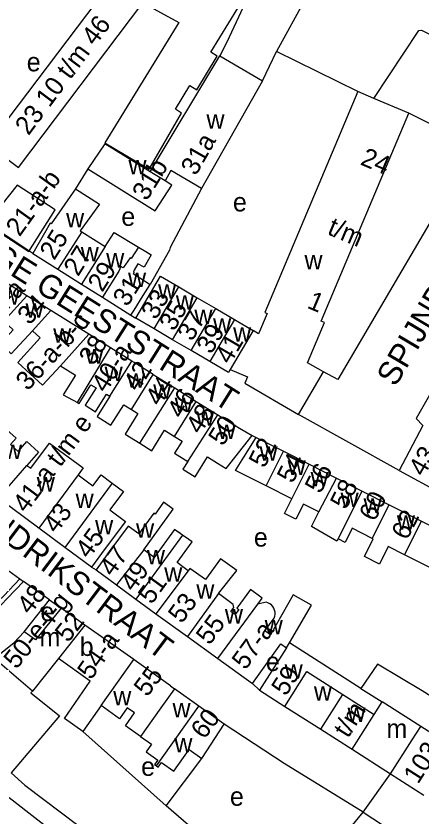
# Model space of a CAD drawing. Extents: x 160673 to 161924, y 382258 to 384145.
# Drawn here: x 160974.8 to 161061.5, y 383019.8 to 383190.7 of the extents above; entities that cross this region are included whole.
import ezdxf

# ---------------------------------------------------------------- set-up
doc = ezdxf.new("R2010")
doc.units = 0
for name, color, linetype in [('BLT_Basislijn', 7, 'Continuous'), ('BLT_Bebouwing', 7, 'Continuous'), ('BLT_Centroide', 7, 'Continuous'), ('BLT_Huisnummer', 7, 'Continuous'), ('BLT_Huisnummer_ tussenligend', 7, 'Continuous'), ('BLT_Huisnummer_reeks', 7, 'Continuous'), ('BLT_Huisnummer_zonder_bebouwing', 7, 'Continuous'), ('BLT_Onderverdeling_panden', 7, 'Continuous'), ('BLT_Plantopo', 7, 'Continuous'), ('BLT_Straatnaam', 7, 'Continuous'), ('BLT_Vlakafsluiter', 7, 'Continuous')]:
    doc.layers.add(name, color=color, linetype=linetype)

msp = doc.modelspace()

# ---------------------------------------------------------------- linework, layer by layer
at = {"layer": 'BLT_Basislijn'}
for p, q in [((161036.77, 383194.74), (161030.43, 383183.09)), ((161027.44, 383176.86), (161030.43, 383183.09)), ((161047.75, 383174.53), (161030.43, 383183.09)), ((161072.75, 383162.91), (161058.69, 383169.92)), ((160990.08, 383158.05), (160987.44, 383153.76)), ((160999.32, 383126.81), (161000.35, 383126.21)), ((161025.23, 383101.17), (161026.06, 383100.78)), ((160990.9, 383073.09), (160991.86, 383072.52)), ((160975.61, 383070.61), (160976.35, 383070.05)), ((160981.93, 383066.1), (160984.38, 383064.36)), ((161026.77, 383046.81), (161025.24, 383048.28)), ((161006.81, 383022.18), (161014.46, 383032.26)), ((161032.47, 383000.08), (161006.81, 383022.18))]:
    msp.add_line(p, q, dxfattribs=at)
for points in [[(161031.09, 383209.4), (161019.81, 383185.12), (161018.27, 383182.14)], [(161051.19, 383173.08), (161060.81, 383187.57), (161061.4, 383187.65), (161069.83, 383183.47), (161071.59, 383182.56)], [(161072.75, 383162.91), (161043.52, 383113.14), (161040.44, 383114.74)], [(161014.37, 383153.9), (161007.71, 383141.3), (161007.56, 383140.71), (161003.41, 383133.39)], [(161088.85, 383154.88), (161060.21, 383104.82), (161061.64, 383103.3)], [(160978.35, 383140.02), (160971.24, 383144.7), (160965.71, 383148.08)], [(161056.57, 383093.7), (161035.09, 383105.63)], [(161048.92, 383020.84), (161032.03, 383031.2), (161019.19, 383039.6)], [(161006.81, 383022.18), (160989.02, 383038.01)], [(160973.74, 383029.17), (160976.69, 383026.54), (161003.35, 383006.47), (160993.29, 382992.74)], [(160963.06, 383015.22), (160978.82, 382996.13), (160992.96, 383008.58), (160973.33, 383023.89)]]:
    msp.add_lwpolyline(points, dxfattribs=at)
at = {"layer": 'BLT_Bebouwing'}
for p, q in [((161003.41, 383157.44), (161018.27, 383182.14)), ((161018.27, 383182.14), (161027.44, 383176.86)), ((161027.44, 383176.86), (161014.37, 383153.9)), ((161051.19, 383173.08), (161047.75, 383174.53)), ((161058.69, 383169.92), (161051.19, 383173.08)), ((161008.02, 383154.59), (161006.6, 383155.47)), ((160988.8, 383144.62), (160993.81, 383141.47)), ((160978.35, 383140.02), (160983.71, 383136.65)), ((160983.71, 383136.65), (160988.78, 383133.46)), ((160977.11, 383130.99), (160972.15, 383134.08)), ((160988.78, 383133.46), (160993.24, 383130.66)), ((161009.52, 383132.88), (161013.49, 383130.56)), ((160982.18, 383127.83), (160977.11, 383130.99)), ((161013.49, 383130.56), (161017.46, 383128.24)), ((161017.46, 383128.24), (161021.43, 383125.91)), ((160990.31, 383122.77), (160982.18, 383127.83)), ((161004.24, 383123.93), (161000.35, 383126.21)), ((161021.43, 383125.91), (161025.4, 383123.59)), ((161008.21, 383121.61), (161004.24, 383123.93)), ((160994.93, 383119.89), (160990.31, 383122.77)), ((161012.18, 383119.28), (161008.21, 383121.61)), ((160999.49, 383117.05), (160994.93, 383119.89)), ((161016.15, 383116.96), (161012.18, 383119.28)), ((161040.44, 383114.74), (161036.99, 383116.65)), ((161035.09, 383105.63), (161040.44, 383114.74)), ((161004.09, 383114.19), (161008.69, 383111.33)), ((161008.69, 383111.33), (161013.28, 383108.46)), ((161013.28, 383108.46), (161017.88, 383105.6)), ((161061.64, 383103.3), (161056.57, 383093.7)), ((161026.06, 383100.78), (161031.89, 383097.82)), ((161031.89, 383097.82), (161037.39, 383095.04)), ((161037.39, 383095.04), (161043.21, 383092.09)), ((161043.21, 383092.09), (161048.7, 383089.3)), ((161056.57, 383093.7), (161073.37, 383084.54)), ((161033.71, 383087.68), (161028.17, 383090.45)), ((161048.7, 383089.3), (161054.43, 383086.4)), ((160979.67, 383081.37), (160970.95, 383087.81)), ((161054.43, 383086.4), (161061.39, 383082.87)), ((161061.39, 383082.87), (161067.01, 383080.02)), ((160985.19, 383077.3), (160979.67, 383081.37)), ((161050.84, 383079.22), (161046.55, 383081.38)), ((160990.9, 383073.09), (160985.19, 383077.3)), ((161063.43, 383072.88), (161057.76, 383075.74)), ((160972.43, 383072.88), (160975.61, 383070.61)), ((160991.86, 383072.52), (160996.21, 383069.3)), ((160981.72, 383066.24), (160976.35, 383070.05)), ((160996.21, 383069.3), (161000.35, 383066.25)), ((160981.93, 383066.1), (160981.72, 383066.24)), ((161028.17, 383065.6), (161026.42, 383065.18)), ((160989.5, 383060.74), (160984.38, 383064.36)), ((161004.66, 383063.13), (161011.39, 383058.28)), ((160999.9, 383053.37), (160989.5, 383060.74)), ((161011.39, 383058.28), (161017.85, 383053.61)), ((161048.44, 383047.22), (161033.17, 383056.94)), ((161032.55, 383055.89), (161026.77, 383046.81)), ((160983.86, 383053.6), (160978.29, 383046.65)), ((161017.85, 383053.61), (161025.24, 383048.28)), ((161007.76, 383047.8), (161008.6, 383047.15)), ((161013.84, 383043.42), (161008.6, 383047.15)), ((161026.77, 383046.81), (161032.17, 383043.37)), ((160992.94, 383043.54), (160989.02, 383038.01)), ((161019.19, 383039.6), (161013.84, 383043.42)), ((161032.17, 383043.37), (161039.85, 383038.49)), ((161039.85, 383038.49), (161046.56, 383034.22)), ((161046.56, 383034.22), (161054.77, 383028.99)), ((161054.77, 383028.99), (161061.89, 383024.47))]:
    msp.add_line(p, q, dxfattribs=at)
for points in [[(161047.75, 383174.53), (161027.92, 383127.43), (161028.41, 383127.23), (161026.58, 383122.88), (161025.4, 383123.59)], [(161036.99, 383116.65), (161040.62, 383125.27), (161039.97, 383125.54), (161058.69, 383169.92)], [(161003.41, 383157.44), (160993.74, 383163.41), (160990.08, 383158.05)], [(160990.08, 383158.05), (161004.49, 383149.13), (161008.02, 383154.59)], [(161014.37, 383153.9), (161007.87, 383157.69), (161006.6, 383155.47)], [(160987.44, 383153.76), (160982.26, 383146.36), (160982.09, 383146.47), (160980.86, 383144.35), (160978.35, 383140.02)], [(160987.44, 383153.76), (160992.6, 383150.52), (160988.48, 383144.82), (160988.8, 383144.62)], [(160993.81, 383141.47), (160995.72, 383144.49), (161000.91, 383141.34)], [(161000.91, 383141.34), (161002.49, 383140.43), (161003.64, 383139.74), (161002.12, 383137.07), (161000.79, 383137.82), (161000, 383136.43), (160999.83, 383136.15), (161000, 383136.05), (160999.8, 383135.73), (161000, 383135.6), (161003.41, 383133.39)], [(161000.35, 383126.21), (161005.6, 383135.18), (161009.52, 383132.88)], [(160999.32, 383126.81), (161000, 383127.9), (161001.96, 383131.06), (161003.41, 383133.39)], [(160993.24, 383130.66), (160996.92, 383128.34), (160999.32, 383126.81)], [(160972.17, 383125.57), (160974.18, 383123.74), (160971.43, 383120.72), (160973.76, 383118.6), (160978.3, 383123.51)], [(160978.3, 383123.51), (160979.94, 383121.98), (160975.15, 383116.73), (160980.44, 383111.9), (160984.24, 383116.06)], [(160984.24, 383116.06), (160987.46, 383114.05), (160984.83, 383109.83), (160987.87, 383108.23)], [(161004.09, 383114.19), (161000.02, 383116.73), (160999.49, 383117.05)], [(161020.48, 383115.25), (161020.12, 383114.64), (161016.15, 383116.96)], [(161020.48, 383115.25), (161024.19, 383113.68), (161023.62, 383112.34), (161035.09, 383105.63)], [(160987.87, 383108.23), (160988.28, 383108.02), (160990.77, 383112.01)], [(160990.77, 383112.01), (160991.86, 383111.33), (160989.56, 383107.64), (160991.78, 383106.25), (160994.11, 383110.02), (160994.83, 383109.57)], [(160994.83, 383109.57), (160992.11, 383105.2), (160995.05, 383103.37), (160997.77, 383107.74), (160999.43, 383106.71)], [(160999.43, 383106.71), (161000, 383106.35), (161000.79, 383105.86), (160998.07, 383101.49), (161001.22, 383099.52)], [(161017.88, 383105.6), (161022.48, 383102.74), (161025.23, 383101.17)], [(160972.18, 383102.98), (160974.82, 383100.58), (160973.58, 383099.22), (160975.2, 383097.74), (160977.06, 383099.92), (160979.58, 383097.62), (160977.11, 383094.8)], [(161001.22, 383099.52), (161003.79, 383097.93), (161006.51, 383102.3), (161008.62, 383100.98)], [(161008.62, 383100.98), (161010.24, 383099.97), (161008.64, 383097.38), (161011.45, 383095.63)], [(161011.45, 383095.63), (161010.42, 383093.97), (161013.01, 383092.36), (161015.64, 383096.61), (161017.81, 383095.26), (161019.66, 383094.11), (161025.23, 383101.17)], [(161028.17, 383090.45), (161021.65, 383093.71), (161023.41, 383096.54), (161026.06, 383100.78)], [(160977.11, 383094.8), (160977.93, 383094.2), (160981.89, 383099.55)], [(160981.89, 383099.55), (160989.11, 383094.25), (160988.03, 383092.8)], [(160988.03, 383092.8), (160991.21, 383090.43), (160992.95, 383092.79), (160995.33, 383091.02)], [(160995.33, 383091.02), (160997.72, 383089.26), (160994.79, 383085.31), (160998.12, 383082.85), (160993.83, 383077.05), (160990.9, 383073.09)], [(161039.47, 383084.89), (161036.16, 383086.55), (161034.55, 383083.35), (161032.14, 383084.56), (161033.71, 383087.68)], [(161002.06, 383076.78), (161008.33, 383085.45), (161006.3, 383086.92), (161004.47, 383084.39), (161004.17, 383084.61), (161000.97, 383080.18), (160999.99, 383080.89), (160998.73, 383081.82), (160994.83, 383076.54), (160991.86, 383072.52)], [(161037.87, 383081.79), (161039.47, 383084.89)], [(161010.36, 383079.89), (161008.61, 383081.15), (161004.29, 383075.17), (161002.06, 383076.78)], [(161009.89, 383080.23), (161009.49, 383080.52)], [(161043.57, 383079.1), (161043.27, 383078.62), (161037.87, 383081.79)], [(161046.55, 383081.38), (161045.03, 383078.36), (161043.57, 383079.1)], [(161010.37, 383073.18), (161009.17, 383074.05), (161012.38, 383078.49), (161011.68, 383079.01), (161010.36, 383079.89)], [(161057.76, 383075.74), (161054.26, 383077.5), (161052.38, 383073.74), (161049.17, 383075.35), (161051.05, 383079.12), (161050.84, 383079.22)], [(161018.01, 383067.44), (161021.9, 383072.39), (161018.45, 383074.88), (161015.22, 383070.42), (161011.92, 383072.8), (161011.57, 383072.31)], [(161011.57, 383072.31), (161010.37, 383073.18)], [(160976.35, 383070.05), (160972.91, 383066.43), (160954.67, 383047.17)], [(160969.3, 383069.58), (160968.81, 383069.05), (160971.62, 383066.39), (160972.18, 383066.98), (160975.61, 383070.61)], [(161026.42, 383065.18), (161027.35, 383066.47), (161024.82, 383068.3), (161021.95, 383064.32), (161022.35, 383064.03), (161021.59, 383062.98), (161020.67, 383063.65), (161021.28, 383064.51), (161021.18, 383065.15), (161018.01, 383067.44)], [(161033.17, 383056.94), (161037.89, 383064.95), (161033.96, 383067.18), (161029.09, 383058.62), (161027.91, 383059.47), (161029.88, 383062.18)], [(160984.38, 383064.36), (160978.91, 383057.58), (160976.49, 383059.3), (160981.93, 383066.1)], [(161000.35, 383066.25), (161004.66, 383063.13)], [(161029.88, 383062.18), (161030.02, 383062.6), (161030.1, 383063.04), (161030.09, 383063.48), (161030, 383063.91), (161029.84, 383064.32), (161029.6, 383064.69), (161029.31, 383065.02), (161028.95, 383065.29), (161028.56, 383065.48), (161028.17, 383065.6)], [(161025.24, 383048.28), (161031.36, 383056.75), (161032.55, 383055.89)], [(160989.02, 383038.01), (160985.13, 383040.77), (160990.62, 383048.78), (160983.86, 383053.6)], [(161007.76, 383047.8), (161000, 383053.29), (160999.9, 383053.37)], [(161077.07, 383036.91), (161072.84, 383039.57), (161061.53, 383046.73), (161051.94, 383052.4), (161048.44, 383047.22)], [(160978.29, 383046.65), (160977.96, 383046.25), (160984.06, 383041.35), (160973.74, 383029.17)], [(161000.06, 383041.97), (160998.5, 383043.07), (160996.87, 383040.76), (160992.94, 383043.54)], [(161001.37, 383036.96), (160998.14, 383039.25), (161000.06, 383041.97)], [(161014.46, 383032.26), (161019.19, 383039.6)], [(161001.37, 383036.96), (161003.69, 383035.32), (161002.54, 383033.71), (161005.05, 383031.92), (161004.38, 383030.98), (161004.77, 383030.7)], [(161004.77, 383030.7), (161005.16, 383030.42), (161005.85, 383031.39), (161008.46, 383029.53), (161011.77, 383034.18), (161014.46, 383032.26)], [(161043.62, 383014.39), (161048.92, 383020.84)], [(161048.92, 383020.84), (161059.68, 383013.78), (161053.76, 383006.58), (161053.83, 383006.39), (161053.58, 383006.1)]]:
    msp.add_lwpolyline(points, dxfattribs=at)
at = {"layer": 'BLT_Onderverdeling_panden'}
for p, q in [((161006.6, 383155.47), (161003.41, 383157.44)), ((160988.8, 383144.62), (160983.71, 383136.65)), ((160993.81, 383141.47), (160988.78, 383133.46)), ((161004.24, 383123.93), (161009.52, 383132.88)), ((160972.17, 383125.57), (160977.11, 383130.99)), ((161008.21, 383121.61), (161013.49, 383130.56)), ((161012.18, 383119.28), (161017.46, 383128.24)), ((160978.3, 383123.51), (160982.18, 383127.83)), ((161021.43, 383125.91), (161016.15, 383116.96)), ((161025.4, 383123.59), (161020.48, 383115.25)), ((160984.24, 383116.06), (160990.31, 383122.77)), ((160987.87, 383108.23), (160994.93, 383119.89)), ((160994.83, 383109.57), (160999.49, 383117.05)), ((160999.43, 383106.71), (161004.09, 383114.19)), ((161001.22, 383099.52), (161008.69, 383111.33)), ((161008.62, 383100.98), (161013.28, 383108.46)), ((161011.45, 383095.63), (161017.88, 383105.6)), ((161028.17, 383090.45), (161031.89, 383097.82)), ((161033.71, 383087.68), (161037.39, 383095.04)), ((160988.03, 383092.8), (160979.67, 383081.37)), ((161039.47, 383084.89), (161043.21, 383092.09)), ((160995.33, 383091.02), (160985.19, 383077.3)), ((161043.57, 383079.1), (161048.7, 383089.3)), ((161050.84, 383079.22), (161054.43, 383086.4)), ((161057.76, 383075.74), (161061.39, 383082.87)), ((161010.36, 383079.89), (161000.35, 383066.25)), ((161002.06, 383076.78), (160996.21, 383069.3)), ((161011.57, 383072.31), (161004.66, 383063.13)), ((161018.01, 383067.44), (161011.39, 383058.28)), ((161017.85, 383053.61), (161026.42, 383065.18)), ((160989.5, 383060.74), (160983.86, 383053.6)), ((161032.55, 383055.89), (161033.17, 383056.94)), ((160978.29, 383046.65), (160970.05, 383053.63)), ((160992.94, 383043.54), (160999.9, 383053.37)), ((161048.44, 383047.22), (161052.99, 383044.33)), ((161039.85, 383038.49), (161044.57, 383045.91)), ((161044.57, 383045.91), (161051.28, 383041.64)), ((161051.28, 383041.64), (161052.99, 383044.33)), ((161061.21, 383039.1), (161052.99, 383044.33)), ((161004.77, 383030.7), (161013.84, 383043.42)), ((161046.56, 383034.22), (161051.28, 383041.64)), ((161059.4, 383036.27), (161061.21, 383039.1)), ((161065.38, 383036.46), (161061.21, 383039.1)), ((161054.77, 383028.99), (161059.4, 383036.27))]:
    msp.add_line(p, q, dxfattribs=at)
for points in [[(161000.91, 383141.34), (160999.35, 383138.9), (160999.13, 383139.09), (160997.67, 383136.92), (160997.17, 383137.25), (160996.72, 383136.2), (160993.24, 383130.66)], [(160970.95, 383087.81), (160977.11, 383094.8)], [(160970.05, 383053.63), (160974.3, 383056.97), (160976.49, 383059.3)], [(161032.17, 383043.37), (161036.9, 383050.79), (161044.57, 383045.91)], [(161008.6, 383047.15), (161005.7, 383043.08), (161001.37, 383036.96)]]:
    msp.add_lwpolyline(points, dxfattribs=at)
at = {"layer": 'BLT_Plantopo'}
for points in [[(161024.06, 383195.51), (161003.48, 383203.75), (160997.11, 383206.28), (160996.26, 383199.42), (160968.78, 383163.17), (160975.31, 383158.38), (161001.86, 383193.48), (161009.53, 383189.28), (160993.76, 383163.64), (161003.18, 383157.96), (161010.1, 383169.97), (161008.8, 383170.77), (161011.89, 383175.83), (161013.36, 383174.93), (161017.76, 383182.13), (161016.4, 383182.96)], [(160975.04, 383154.55), (160968.39, 383146.31), (160977.54, 383140.46), (160983.13, 383149.33)]]:
    msp.add_lwpolyline(points, close=True, dxfattribs=at)
at = {"layer": 'BLT_Vlakafsluiter'}
msp.add_line((161048.92, 383020.84), (161054.77, 383028.99), dxfattribs=at)

# ---------------------------------------------------------------- texts
at = {"layer": 'BLT_Centroide'}
for s, p in [('e', (160977.06, 383178.86)), ('w', (161015.44, 383166.61)), ('w', (160998.78, 383156.88)), ('e', (161021.1, 383148.98)), ('w', (160985.47, 383145.58)), ('e', (160997.26, 383145.9)), ('w', (160988.59, 383138.34)), ('w', (160994.03, 383137)), ('w', (161036.37, 383136.63)), ('w', (160998.69, 383132.83)), ('w', (161005.1, 383130.37)), ('w', (160971.66, 383129.09)), ('w', (161008.9, 383128.03)), ('w', (160976.81, 383126.3)), ('w', (161012.86, 383124.91)), ('w', (161016.86, 383123.07)), ('w', (160982.72, 383120.95)), ('w', (161021.14, 383121.17)), ('w', (160989.58, 383116.52)), ('w', (160993.69, 383112.78)), ('w', (160998.48, 383111.36)), ('w', (161004.06, 383109.02)), ('w', (161008.66, 383106.16)), ('w', (161013.25, 383103.28)), ('w', (161017.84, 383100.44)), ('w', (160972.19, 383096.14)), ('w', (161026.77, 383095.78)), ('w', (161032.78, 383092.77)), ('w', (160979.2, 383089.22)), ('w', (161037.67, 383090.34)), ('w', (160987.5, 383085.7)), ('w', (161044.08, 383085.89)), ('w', (161049, 383084.66)), ('w', (161056.11, 383081.05)), ('w', (160991.66, 383080.06)), ('w', (161000.41, 383079.34)), ('e', (161025.57, 383077.47)), ('w', (161002.73, 383073.69)), ('w', (161006.42, 383069.98)), ('w', (161013.28, 383066.36)), ('e', (160979.98, 383061.59)), ('w', (161019.38, 383061.06)), ('w', (161027.88, 383058.72)), ('m', (160979.78, 383056.16)), ('b', (160988.38, 383054.14)), ('e', (161028.13, 383050.93)), ('w', (161032.14, 383049.28)), ('w', (161038.38, 383044.62)), ('w', (160995.53, 383043.58)), ('w', (161008.19, 383041.03)), ('w', (161045.56, 383040.06)), ('m', (161053.88, 383036.66)), ('w', (161008.59, 383033.56)), ('e', (161001.49, 383028.56)), ('e', (161020.46, 383022.18))]:
    msp.add_text(s, height=4, dxfattribs=at).set_placement(p)
at = {"layer": 'BLT_Huisnummer'}
for s, rotation, p in [('31a', 60.3458, (161013.19, 383156.41)), ('31b', 58.3696, (161002.7, 383151.04)), ('25', 57.8543, (160982.93, 383138.39)), ('31', 58.1301, (160998.56, 383128.47)), ('33', 59.6614, (161004.67, 383125.67)), ('34', 47.6104, (160977.63, 383124.56)), ('37', 59.6614, (161012.39, 383121.08)), ('38', 58.0561, (160991.32, 383115.91)), ('41', 59.6614, (161020.49, 383116.15)), ('42', 58.0876, (161000.83, 383110.35)), ('46', 58.0876, (161010.14, 383104.55)), ('50', 58.0869, (161018.96, 383098.72)), ('52', 63.4567, (161027.83, 383094.03)), ('56', 63.4539, (161039.81, 383088.59)), ('60', 62.8658, (161051.36, 383082.63)), ('43', 53.526, (160983.4, 383080.07)), ('45', 53.521, (160990.32, 383074.68)), ('47', 54.1172, (160995.42, 383070.86)), ('51', 54.1172, (161003.73, 383064.96)), ('55', 53.4597, (161016.09, 383056.27)), ('55', 53.4597, (161002.81, 383045.23)), ('60', 53.4597, (161014.99, 383036.18))]:
    msp.add_text(s, height=4, rotation=rotation, dxfattribs=at).set_placement(p)
at = {"layer": 'BLT_Huisnummer_ tussenligend'}
for s, rotation, p in [('27', 57.8547, (160988.03, 383134.92)), ('29', 57.8547, (160993.2, 383131.58)), ('35', 59.6614, (161008.52, 383123.23)), ('39', 59.6614, (161016.48, 383118.34)), ('44', 58.0876, (161005.48, 383107.22)), ('48', 58.0876, (161014.14, 383101.23)), ('54', 63.4567, (161033.86, 383090.77)), ('58', 63.4539, (161045.23, 383085.18)), ('62', 62.8658, (161058.28, 383078.66)), ('49', 54.1172, (160999.89, 383067.63)), ('53', 54.1172, (161010.17, 383060.87))]:
    msp.add_text(s, height=4, rotation=rotation, dxfattribs=at).set_placement(p)
at = {"layer": 'BLT_Huisnummer_reeks'}
for s, rotation, p in [('24', 337.1329, (161048.11, 383159.04)), ('t/m', 337.1329, (161041.04, 383144.2)), ('32-a', 47.6128, (160969.72, 383124.31)), ('1', 337.1329, (161036.73, 383128.47)), ('36-a-b-c', 47.6104, (160977.29, 383110.53)), ('40-a', 58.0561, (160993.97, 383110.08)), ('43-a-b', 60.3796, (161061.84, 383092.22)), ('41-a t/m e', 53.4884, (160976.94, 383084.45)), ('48', 51.332, (160977.73, 383062.74)), ('50-e-f-g', 51.2855, (160974.88, 383051.15)), ('52', 51.6962, (160985.88, 383056.82)), ('57-a', 54.125, (161023.78, 383050.97)), ('54-a', 54.6847, (160990.81, 383048.86)), ('59 ', 57.5403, (161032.4, 383045.38)), ('t/m', 57.5394, (161045.67, 383036.44)), ('103', 57.5394, (161060.62, 383026.64))]:
    msp.add_text(s, height=4, rotation=rotation, dxfattribs=at).set_placement(p)
at = {"layer": 'BLT_Huisnummer_zonder_bebouwing'}
for s, rotation, p in [('23 10 t/m 46', 53.3445, (160977.44, 383165.01)), ('21-a-b', 54.3445, (160975.53, 383143.41))]:
    msp.add_text(s, height=4, rotation=rotation, dxfattribs=at).set_placement(p)
at = {"layer": 'BLT_Straatnaam'}
for s, height, rotation, p in [('HEILIGE GEESTSTRAAT', 4.9999, 327.8233, (160954.72, 383147.22)), ('SPIJNDHOF', 5, 59.3864, (161055.8, 383111.35)), ('PRINS HENDRIKSTRAAT', 5, 322.9311, (160942.95, 383100.57))]:
    msp.add_text(s, height=height, rotation=rotation, dxfattribs=at).set_placement(p)

doc.saveas('drawing.dxf')
